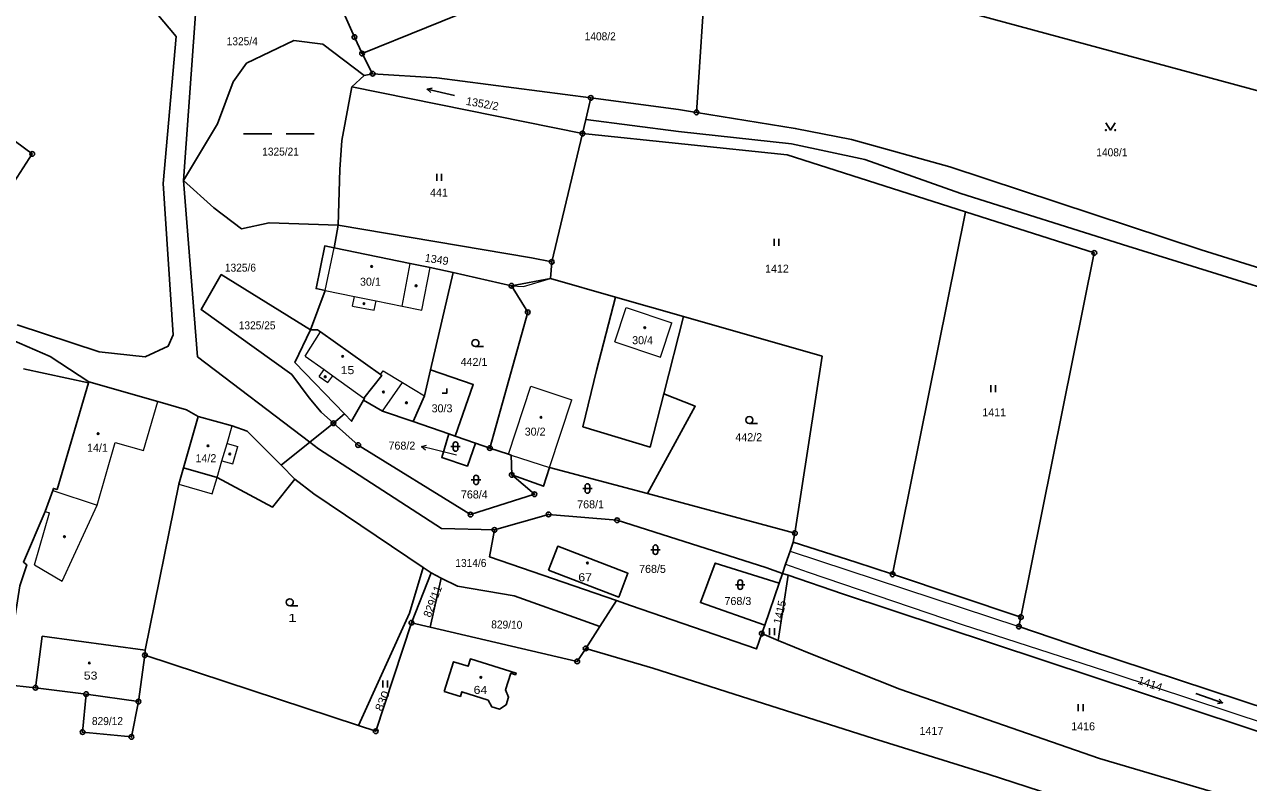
# Model space of a CAD drawing. Extents: x -872229 to -869198, y -1075981 to -1074329.
# Drawn here: x -870924.3 to -870664.3, y -1075366 to -1075205 of the extents above; entities that cross this region are included whole.
import ezdxf
from ezdxf.enums import TextEntityAlignment as Align

# ---------------------------------------------------------------- set-up
doc = ezdxf.new("R2010")
doc.units = 0
doc.header["$LTSCALE"] = 0.68
for name, color, linetype, lineweight in [('1', 7, 'Continuous', 25), ('3', 7, 'Continuous', 25), ('4', 7, 'Continuous', 13), ('5', 7, 'Continuous', 25), ('7', 7, 'Continuous', 13), ('8', 7, 'Continuous', 25)]:
    doc.layers.add(name, color=color, linetype=linetype, lineweight=lineweight)
doc.layers.add('2', color=7, linetype='Continuous')

msp = doc.modelspace()

# ---------------------------------------------------------------- linework, layer by layer
at = {"layer": '1'}
for p, q in [((-870784.32, -1075186.07), (-870610.3, -1075233.15)), ((-870850.35, -1075215.5), (-870852.61, -1075211.21)), ((-870854.77, -1075218.26), (-870852.13, -1075215.85)), ((-870857.69, -1075247.67), (-870858.56, -1075252.46)), ((-870838.03, -1075278.35), (-870833.27, -1075257.72)), ((-870788.49, -1075283.45), (-870784.32, -1075267.06)), ((-870910.7, -1075281.16), (-870924.55, -1075278.18)), ((-870858.68, -1075289.72), (-870856.35, -1075287.73)), ((-870858.68, -1075289.72), (-870863.7, -1075293.77)), ((-870869.76, -1075298.66), (-870863.7, -1075293.77)), ((-870866.86, -1075301.57), (-870869.76, -1075298.66)), ((-870791.98, -1075304.67), (-870760.65, -1075313.06)), ((-870921.99, -1075345.91), (-870928.54, -1075345.19))]:
    msp.add_line(p, q, dxfattribs=at)
for points in [[(-870852.61, -1075211.21), (-870811.58, -1075194.57), (-870784.32, -1075186.07)], [(-870811.58, -1075194.57), (-870779.53, -1075192.5), (-870781.56, -1075223.68)], [(-870925.85, -1075268.83), (-870908.47, -1075274.58), (-870898.66, -1075275.61), (-870893.76, -1075273.35), (-870892.7, -1075270.97), (-870894.88, -1075238.8), (-870892.1, -1075207.59), (-870896.18, -1075202.7), (-870909.34, -1075202.24), (-870920.27, -1075200.54), (-870931.8, -1075197.32)], [(-870882.08, -1075195.84), (-870887.87, -1075200.84), (-870890.54, -1075238.17)], [(-870852.61, -1075211.21), (-870854.23, -1075207.71), (-870856.49, -1075202.6)], [(-870890.54, -1075238.17), (-870883.32, -1075226.14), (-870879.96, -1075217.21), (-870877.12, -1075213.23), (-870867.09, -1075208.41), (-870860.94, -1075209.18), (-870852.13, -1075215.85), (-870850.35, -1075215.5)], [(-870804.02, -1075220.62), (-870836.74, -1075216.34), (-870850.35, -1075215.5)], [(-870857.69, -1075247.67), (-870816.62, -1075254.62), (-870812.3, -1075255.46), (-870805.78, -1075228.2), (-870854.77, -1075218.26)], [(-870854.77, -1075218.26), (-870856.87, -1075229.66), (-870857.34, -1075235.8), (-870857.69, -1075247.67)], [(-870805.78, -1075228.2), (-870805.08, -1075225.21), (-870804.02, -1075220.62)], [(-870781.56, -1075223.68), (-870785.37, -1075223.06), (-870804.02, -1075220.62)], [(-870484.94, -1075312.75), (-870507.19, -1075305.67), (-870536.45, -1075296.46), (-870573.82, -1075284.57), (-870611.19, -1075272.67), (-870674.35, -1075252.89), (-870727.76, -1075235.26), (-870748.62, -1075229.44), (-870760.57, -1075227.08), (-870781.56, -1075223.68)], [(-870805.08, -1075225.21), (-870785.38, -1075227.74), (-870761.4, -1075230.4), (-870745.77, -1075233.67), (-870725.43, -1075240.95), (-870689.94, -1075252.08), (-870636.2, -1075268.85), (-870577.25, -1075287.24), (-870525.79, -1075303.65), (-870498.58, -1075312.54)], [(-870805.78, -1075228.2), (-870762.33, -1075232.72), (-870724.39, -1075244.81)], [(-871072.01, -1075232.97), (-871066.83, -1075229.86), (-871050.73, -1075230.05), (-871024.91, -1075235.65), (-871004.91, -1075242.17), (-870984.75, -1075250.58), (-870962.8, -1075257.63), (-870944.86, -1075263.23), (-870926.98, -1075271.99), (-870918.87, -1075275.55), (-870910.63, -1075280.9)], [(-870863.7, -1075293.77), (-870887.53, -1075275.59), (-870890.54, -1075238.17)], [(-870890.54, -1075238.17), (-870884.1, -1075243.98), (-870878.24, -1075248.43), (-870872.37, -1075247.14), (-870857.69, -1075247.67)], [(-870724.39, -1075244.81), (-870739.92, -1075321.81), (-870712.65, -1075330.89)], [(-870724.39, -1075244.81), (-870697.05, -1075253.53), (-870712.65, -1075330.89)], [(-870858.56, -1075252.46), (-870860.52, -1075252.06), (-870862.38, -1075261.13), (-870860.42, -1075261.53), (-870863.57, -1075269.88)], [(-870833.27, -1075257.72), (-870838.15, -1075256.62), (-870842.37, -1075255.78), (-870858.56, -1075252.46)], [(-870833.27, -1075257.72), (-870820.86, -1075260.51), (-870812.59, -1075258.97), (-870812.3, -1075255.46)], [(-870858.68, -1075289.72), (-870861.31, -1075287.4), (-870863.81, -1075284.33), (-870867.54, -1075279.36), (-870886.81, -1075265.58), (-870882.51, -1075258.13), (-870863.57, -1075269.88)], [(-870812.59, -1075258.97), (-870798.73, -1075262.94), (-870784.32, -1075267.06)], [(-870820.86, -1075260.51), (-870817.4, -1075266.16), (-870825.46, -1075294.99)], [(-870788.49, -1075283.45), (-870791.37, -1075294.77), (-870805.69, -1075290.46), (-870802.78, -1075278.5), (-870798.73, -1075262.94)], [(-870784.32, -1075267.06), (-870754.88, -1075275.48), (-870760.65, -1075313.06), (-870761.04, -1075314.99)], [(-870863.57, -1075269.88), (-870866.86, -1075276.84), (-870856.35, -1075287.73)], [(-870863.57, -1075269.88), (-870862.1, -1075269.86), (-870861.44, -1075270.33), (-870848.69, -1075279.37), (-870848.43, -1075279.55), (-870852.2, -1075284.38), (-870852.07, -1075284.47), (-870852.32, -1075284.82)], [(-870841.73, -1075289.35), (-870839.31, -1075283.9), (-870838.03, -1075278.35)], [(-870832.79, -1075292.45), (-870828.99, -1075281.49), (-870838.03, -1075278.35)], [(-870887.42, -1075288.26), (-870889.87, -1075286.84), (-870896.02, -1075285.08), (-870910.63, -1075280.9), (-870910.7, -1075281.16)], [(-870910.7, -1075281.16), (-870917.39, -1075303.79), (-870918.16, -1075303.57), (-870918.31, -1075303.99), (-870919.9, -1075308.44)], [(-870791.98, -1075304.67), (-870781.81, -1075286.11), (-870788.49, -1075283.45)], [(-870856.35, -1075287.73), (-870854.84, -1075289.29), (-870852.32, -1075284.82)], [(-870852.32, -1075284.82), (-870848.28, -1075287.16), (-870841.73, -1075289.35)], [(-870869.76, -1075298.66), (-870877.02, -1075291.38), (-870880.21, -1075290.3), (-870887.42, -1075288.26), (-870890.53, -1075299.22)], [(-870820.81, -1075300.7), (-870815.99, -1075304.8), (-870829.56, -1075309.11), (-870853.43, -1075294.36), (-870858.68, -1075289.72)], [(-870841.73, -1075289.35), (-870834.19, -1075291.97), (-870832.79, -1075292.45)], [(-870863.7, -1075293.77), (-870861.84, -1075295.19), (-870835.74, -1075312.07), (-870824.47, -1075312.39)], [(-870834.19, -1075291.97), (-870835.68, -1075297.01), (-870830.23, -1075298.81), (-870828.5, -1075293.94)], [(-870832.79, -1075292.45), (-870828.5, -1075293.94), (-870825.46, -1075294.99)], [(-870825.46, -1075294.99), (-870821.46, -1075296.31), (-870820.92, -1075296.51), (-870820.81, -1075300.7)], [(-870898.66, -1075337.89), (-870891.52, -1075302.69), (-870890.53, -1075299.22)], [(-870890.53, -1075299.22), (-870883.4, -1075301.25), (-870871.64, -1075307.56), (-870866.86, -1075301.57)], [(-870820.81, -1075300.7), (-870814.03, -1075303.11), (-870812.79, -1075299.09), (-870791.98, -1075304.67)], [(-870839.61, -1075320.36), (-870862.82, -1075304.74), (-870866.86, -1075301.57)], [(-870919.9, -1075308.44), (-870924.53, -1075319.22), (-870923.81, -1075319.83), (-870925.29, -1075324.27), (-870928.54, -1075345.19)], [(-870824.47, -1075312.39), (-870812.98, -1075309.08), (-870798.44, -1075310.32), (-870766.82, -1075320.38), (-870763.32, -1075321.65)], [(-870798.57, -1075327.39), (-870825.5, -1075318.12), (-870824.47, -1075312.39)], [(-870712.65, -1075330.89), (-870713.06, -1075332.91), (-870698.73, -1075337.79), (-870659.43, -1075350.77), (-870647.08, -1075354.82), (-870636.39, -1075356.51), (-870628.42, -1075355.25), (-870617.68, -1075352.56), (-870583.59, -1075341.47), (-870525.05, -1075322.56), (-870498.58, -1075312.54)], [(-870761.04, -1075314.99), (-870761.68, -1075316.88), (-870762.63, -1075319.63), (-870763.32, -1075321.65), (-870762.07, -1075321.97)], [(-870761.04, -1075314.99), (-870747.73, -1075319.21), (-870739.92, -1075321.81)], [(-870764.02, -1075323.7), (-870777.56, -1075319.43), (-870780.71, -1075327.83), (-870767.06, -1075332.59)], [(-870853.39, -1075353.92), (-870842.55, -1075330.06), (-870839.61, -1075320.36)], [(-870842.12, -1075332.11), (-870837.92, -1075321.5), (-870839.61, -1075320.36)], [(-870838.12, -1075333.04), (-870835.78, -1075322.6), (-870837.92, -1075321.5)], [(-870835.78, -1075322.6), (-870832.36, -1075324.35), (-870820.31, -1075326.41), (-870805.66, -1075331.61), (-870802.09, -1075332.87)], [(-870763.32, -1075321.65), (-870764.02, -1075323.7), (-870767.06, -1075332.59), (-870767.68, -1075334.4), (-870764.18, -1075335.84), (-870762.07, -1075321.97)], [(-870762.07, -1075321.97), (-870750.55, -1075325.97), (-870644.01, -1075361.21), (-870635.72, -1075362.14)], [(-870798.57, -1075327.39), (-870802.09, -1075332.87), (-870805.1, -1075337.55)], [(-870798.57, -1075327.39), (-870795.56, -1075328.43), (-870768.8, -1075337.66), (-870767.68, -1075334.4)], [(-870842.12, -1075332.11), (-870849.71, -1075355.13), (-870853.39, -1075353.92), (-870898.74, -1075339.01)], [(-870805.1, -1075337.55), (-870806.88, -1075340.32), (-870838.12, -1075333.04), (-870842.12, -1075332.11)], [(-870898.66, -1075337.89), (-870920.55, -1075334.96), (-870921.99, -1075345.91)], [(-870921.99, -1075345.91), (-870911.24, -1075347.26), (-870900.1, -1075348.84), (-870898.74, -1075339.01), (-870898.66, -1075337.89)], [(-870805.1, -1075337.55), (-870790.85, -1075341.74), (-870773.54, -1075347.26), (-870743.94, -1075356.68), (-870719.6, -1075364.23), (-870689.31, -1075374.07), (-870671.81, -1075380.32), (-870663.52, -1075383.76), (-870658.58, -1075387.02), (-870652.84, -1075392.9), (-870644.86, -1075404.62), (-870633.82, -1075423.29), (-870622.61, -1075439.76), (-870615.24, -1075449.79), (-870605.9, -1075460.53), (-870599.41, -1075465.72), (-870590.82, -1075469.8), (-870575.95, -1075474.7)], [(-870764.18, -1075335.84), (-870757.26, -1075338.7), (-870738.34, -1075346.2), (-870695.93, -1075360.93), (-870670.53, -1075368.46), (-870660.23, -1075373.2), (-870649.84, -1075380.47), (-870640.68, -1075391.97)], [(-870911.24, -1075347.26), (-870911.97, -1075355.32), (-870901.6, -1075356.36), (-870900.1, -1075348.84)]]:
    msp.add_lwpolyline(points, dxfattribs=at)
for points in [[(-870939.42, -1075220.15), (-870948.22, -1075229.84), (-870930.39, -1075244.42), (-870922.66, -1075232.5)], [(-870812.99, -1075320.94), (-870811.04, -1075315.85), (-870796.14, -1075321.57), (-870798.09, -1075326.66)], [(-870835.15, -1075346.69), (-870833.2, -1075340.38), (-870830.05, -1075341.35), (-870829.57, -1075339.79), (-870819.89, -1075342.79), (-870820.01, -1075343.15), (-870821.02, -1075342.83), (-870822.13, -1075346.38), (-870821.48, -1075347.92), (-870822.01, -1075349.53), (-870823.39, -1075350.47), (-870825.02, -1075349.98), (-870825.84, -1075348.52), (-870831.38, -1075346.75), (-870831.7, -1075347.75)]]:
    msp.add_lwpolyline(points, close=True, dxfattribs=at)
at = {"layer": '3'}
for p, q in [((-870838.798, -1075218.783), (-870837.733, -1075218.514)), ((-870877.759, -1075228.27), (-870871.759, -1075228.27)), ((-870868.759, -1075228.27), (-870862.759, -1075228.27)), ((-870836.751, -1075238.26), (-870836.751, -1075236.76)), ((-870835.75, -1075238.26), (-870835.75, -1075236.76)), ((-870765.051, -1075252.05), (-870765.051, -1075250.55)), ((-870764.05, -1075252.05), (-870764.05, -1075250.55)), ((-870828.523, -1075273.44), (-870826.773, -1075273.44)), ((-870719.011, -1075283.15), (-870719.011, -1075281.65)), ((-870718.01, -1075283.15), (-870718.01, -1075281.65)), ((-870770.343, -1075289.79), (-870768.593, -1075289.79)), ((-870833.741, -1075294.671), (-870831.739, -1075294.671)), ((-870833.241, -1075294.171), (-870833.241, -1075295.172)), ((-870832.239, -1075295.172), (-870832.239, -1075294.171)), ((-870829.391, -1075301.751), (-870827.389, -1075301.751)), ((-870828.891, -1075301.251), (-870828.891, -1075302.252)), ((-870827.889, -1075302.252), (-870827.889, -1075301.251)), ((-870805.721, -1075303.581), (-870803.719, -1075303.581)), ((-870805.221, -1075303.081), (-870805.221, -1075304.082)), ((-870804.219, -1075304.082), (-870804.219, -1075303.081)), ((-870791.281, -1075316.581), (-870789.279, -1075316.581)), ((-870790.781, -1075316.081), (-870790.781, -1075317.082)), ((-870789.779, -1075317.082), (-870789.779, -1075316.081)), ((-870773.271, -1075324.011), (-870771.269, -1075324.011)), ((-870772.771, -1075323.511), (-870772.771, -1075324.512)), ((-870771.769, -1075324.512), (-870771.769, -1075323.511)), ((-870867.963, -1075328.5), (-870866.213, -1075328.5)), ((-870766.021, -1075334.75), (-870766.021, -1075333.25)), ((-870765.02, -1075334.75), (-870765.02, -1075333.25)), ((-870848.171, -1075345.86), (-870848.171, -1075344.36)), ((-870847.17, -1075345.86), (-870847.17, -1075344.36)), ((-870700.451, -1075350.89), (-870700.451, -1075349.39)), ((-870699.45, -1075350.89), (-870699.45, -1075349.39)), ((-870669.79, -1075349.09), (-870670.877, -1075349.246))]:
    msp.add_line(p, q, dxfattribs=at)
for points in [[(-870832.952, -1075220.133), (-870838.798, -1075218.783), (-870837.959, -1075219.491)], [(-870694.6, -1075225.939), (-870693.6, -1075227.44), (-870692.6, -1075225.939)], [(-870835.591, -1075283.33), (-870834.59, -1075283.33), (-870834.59, -1075282.33)], [(-870675.463, -1075347.137), (-870669.79, -1075349.09), (-870670.551, -1075348.298)]]:
    msp.add_lwpolyline(points, dxfattribs=at)
for centre, radius in [((-870694.6, -1075227.4395), 0.1), ((-870692.6, -1075227.4395), 0.1), ((-870828.5229, -1075272.6898), 0.75), ((-870770.3429, -1075289.0398), 0.75), ((-870867.9629, -1075327.7498), 0.75)]:
    msp.add_circle(centre, radius, dxfattribs=at)
for centre, start, end in [((-870832.74, -1075294.1709), 0, 180), ((-870832.74, -1075295.1709), 180, 359.98789), ((-870828.39, -1075301.2509), 0, 180), ((-870828.39, -1075302.2509), 180, 359.98789), ((-870804.72, -1075303.0809), 0, 180), ((-870804.72, -1075304.0809), 180, 359.98789), ((-870790.28, -1075316.0809), 0, 180), ((-870790.28, -1075317.0809), 180, 359.98789), ((-870772.27, -1075323.5109), 0, 180), ((-870772.27, -1075324.5109), 180, 359.98789)]:
    msp.add_arc(centre, 0.5, start, end, dxfattribs=at)
at = {"layer": '4'}
for p, q in [((-870860.42, -1075261.53), (-870858.56, -1075252.46)), ((-870844.1, -1075264.84), (-870842.37, -1075255.78)), ((-870839.87, -1075265.69), (-870838.15, -1075256.62)), ((-870860.42, -1075261.53), (-870854.21, -1075262.79)), ((-870854.65, -1075264.85), (-870850.05, -1075265.73)), ((-870844.1, -1075264.84), (-870839.87, -1075265.69)), ((-870798.93, -1075272.46), (-870796.52, -1075265.16)), ((-870796.52, -1075265.16), (-870786.8, -1075268.38)), ((-870864.7, -1075275.44), (-870861.44, -1075270.33)), ((-870789.18, -1075275.68), (-870786.8, -1075268.38)), ((-870798.93, -1075272.46), (-870789.18, -1075275.68)), ((-870864.7, -1075275.44), (-870860.66, -1075278.33)), ((-870861.69, -1075279.77), (-870859.85, -1075281.09)), ((-870848.69, -1075279.37), (-870848.13, -1075278.57)), ((-870848.13, -1075278.57), (-870843.98, -1075281.08)), ((-870848.28, -1075287.16), (-870843.98, -1075281.08)), ((-870843.98, -1075281.08), (-870839.31, -1075283.9)), ((-870821.46, -1075296.31), (-870816.74, -1075281.81)), ((-870816.74, -1075281.81), (-870808.05, -1075284.73)), ((-870899.02, -1075295.53), (-870896.02, -1075285.08)), ((-870812.79, -1075299.09), (-870808.05, -1075284.73)), ((-870881.29, -1075294.02), (-870880.21, -1075290.3)), ((-870880.04, -1075298.35), (-870878.97, -1075294.69)), ((-870820.92, -1075296.51), (-870812.79, -1075299.09)), ((-870918.31, -1075303.99), (-870908.88, -1075307.14)), ((-870922.2, -1075319.79), (-870918.98, -1075308.77)), ((-870919.9, -1075308.44), (-870918.98, -1075308.77)), ((-870916.32, -1075323.29), (-870908.88, -1075307.14)), ((-870761.68, -1075316.88), (-870713.06, -1075332.91)), ((-870922.2, -1075319.79), (-870916.32, -1075323.29)), ((-870725.1, -1075332.47), (-870692.51, -1075343.01)), ((-870692.51, -1075343.01), (-870660.32, -1075353.61))]:
    msp.add_line(p, q, dxfattribs=at)
for points in [[(-870820.86, -1075260.51), (-870818.3, -1075260.71), (-870812.59, -1075258.97)], [(-870854.65, -1075264.85), (-870854.21, -1075262.79), (-870849.64, -1075263.72)], [(-870850.05, -1075265.73), (-870849.64, -1075263.72), (-870844.1, -1075264.84)], [(-870861.69, -1075279.77), (-870860.66, -1075278.33), (-870858.82, -1075279.65)], [(-870859.85, -1075281.09), (-870858.82, -1075279.65), (-870852.2, -1075284.38)], [(-870908.88, -1075307.14), (-870905.02, -1075293.81), (-870899.02, -1075295.53)], [(-870882.36, -1075297.68), (-870881.29, -1075294.02), (-870878.97, -1075294.69)], [(-870891.52, -1075302.69), (-870884.41, -1075304.73), (-870883.4, -1075301.25), (-870882.36, -1075297.68), (-870880.04, -1075298.35)], [(-870762.63, -1075319.63), (-870757.87, -1075321.38), (-870725.1, -1075332.47)]]:
    msp.add_lwpolyline(points, dxfattribs=at)
at = {"layer": '5'}
for centre in [(-870850.5468, -1075256.4092), (-870841.1168, -1075260.5292), (-870852.1768, -1075264.3292), (-870792.5368, -1075269.4292), (-870856.7368, -1075275.5092), (-870860.4268, -1075279.8492), (-870848.0568, -1075283.0992), (-870843.1768, -1075285.3792), (-870814.6068, -1075288.4492), (-870908.6768, -1075291.9292), (-870885.3168, -1075294.5192), (-870880.6968, -1075296.2492), (-870915.8168, -1075313.8192), (-870804.7168, -1075319.4192), (-870910.5268, -1075340.6392), (-870827.3568, -1075343.6992)]:
    msp.add_circle(centre, 0.175, dxfattribs=at)
at = {"layer": '7'}
msp.add_line((-870839.992, -1075294.644), (-870839.141, -1075295.372), dxfattribs=at)
msp.add_lwpolyline([(-870832.55, -1075296.49), (-870837.08, -1075295.37), (-870839.992, -1075294.644), (-870838.899, -1075294.4)], dxfattribs=at)
at = {"layer": '8'}
for centre, radius in [((-870854.23, -1075207.7099), 0.5), ((-870854.23, -1075207.7099), 0.0303), ((-870852.61, -1075211.2099), 0.5), ((-870852.61, -1075211.2099), 0.0303), ((-870850.35, -1075215.4999), 0.5), ((-870850.35, -1075215.4999), 0.0303), ((-870804.02, -1075220.6199), 0.5), ((-870804.02, -1075220.6199), 0.0303), ((-870781.56, -1075223.6799), 0.5), ((-870781.56, -1075223.6799), 0.0303), ((-870805.78, -1075228.1999), 0.5), ((-870805.78, -1075228.1999), 0.0303), ((-870922.66, -1075232.4999), 0.5), ((-870922.66, -1075232.4999), 0.0303), ((-870812.3, -1075255.4599), 0.5), ((-870697.05, -1075253.5299), 0.5), ((-870697.05, -1075253.5299), 0.0303), ((-870812.3, -1075255.4599), 0.0303), ((-870820.86, -1075260.5099), 0.5), ((-870820.86, -1075260.5099), 0.0303), ((-870817.4, -1075266.1599), 0.5), ((-870817.4, -1075266.1599), 0.0303), ((-870858.68, -1075289.7199), 0.5), ((-870858.68, -1075289.7199), 0.0303), ((-870853.43, -1075294.3599), 0.5), ((-870853.43, -1075294.3599), 0.0303), ((-870825.46, -1075294.9899), 0.5), ((-870825.46, -1075294.9899), 0.0303), ((-870820.81, -1075300.6999), 0.5), ((-870820.81, -1075300.6999), 0.0303), ((-870815.99, -1075304.7999), 0.5), ((-870815.99, -1075304.7999), 0.0303), ((-870829.56, -1075309.1099), 0.5), ((-870829.56, -1075309.1099), 0.0303), ((-870812.98, -1075309.0799), 0.5), ((-870812.98, -1075309.0799), 0.0303), ((-870824.47, -1075312.3899), 0.5), ((-870798.44, -1075310.3199), 0.5), ((-870798.44, -1075310.3199), 0.0303), ((-870824.47, -1075312.3899), 0.0303), ((-870760.65, -1075313.0599), 0.5), ((-870760.65, -1075313.0599), 0.0303), ((-870739.92, -1075321.8099), 0.5), ((-870739.92, -1075321.8099), 0.0303), ((-870712.65, -1075330.8899), 0.5), ((-870842.12, -1075332.1099), 0.5), ((-870842.12, -1075332.1099), 0.0303), ((-870713.06, -1075332.9099), 0.5), ((-870713.06, -1075332.9099), 0.0303), ((-870712.65, -1075330.8899), 0.0303), ((-870767.68, -1075334.3999), 0.5), ((-870767.68, -1075334.3999), 0.0303), ((-870805.1, -1075337.5499), 0.5), ((-870805.1, -1075337.5499), 0.0303), ((-870898.74, -1075339.0099), 0.5), ((-870898.74, -1075339.0099), 0.0303), ((-870806.88, -1075340.3199), 0.5), ((-870806.88, -1075340.3199), 0.0303), ((-870921.99, -1075345.9099), 0.5), ((-870921.99, -1075345.9099), 0.0303), ((-870911.24, -1075347.2599), 0.5), ((-870911.24, -1075347.2599), 0.0303), ((-870900.1, -1075348.8399), 0.5), ((-870900.1, -1075348.8399), 0.0303), ((-870911.97, -1075355.3199), 0.5), ((-870911.97, -1075355.3199), 0.0303), ((-870901.6, -1075356.3599), 0.5), ((-870901.6, -1075356.3599), 0.0303), ((-870849.71, -1075355.1299), 0.5), ((-870849.71, -1075355.1299), 0.0303)]:
    msp.add_circle(centre, radius, dxfattribs=at)

# ---------------------------------------------------------------- texts
at = {"layer": '2'}
for s, width, p in [('1325/4', 0.95, (-870881.36, -1075209.43)), ('1325/21', 0.95, (-870873.82, -1075232.87)), ('1325/6', 0.95, (-870881.74, -1075257.52)), ('1325/25', 0.95, (-870878.8, -1075269.78)), ('15', 1.15, (-870857.16, -1075279.29)), ('1314/6', 0.95, (-870832.79, -1075320.25)), ('1', 1.45, (-870868.33, -1075331.91)), ('53', 1.15, (-870911.72, -1075344.17)), ('829/12', 0.95, (-870909.99, -1075353.83))]:
    msp.add_text(s, height=1.7, dxfattribs=dict(at, width=width)).set_placement(p)
for s, width, p in [('1408/2', 0.95, (-870802.009, -1075208.39)), ('1408/1', 0.95, (-870693.319, -1075233.03)), ('67', 1.15, (-870805.21, -1075323.28)), ('64', 1.15, (-870827.45, -1075347.21))]:
    msp.add_text(s, height=1.7, dxfattribs=dict(at, width=width)).set_placement(p, align=Align.CENTER)
for s, rotation, p in [('1352/2', 350, (-870830.617, -1075222.077)), ('1349', 351, (-870839.372, -1075255.369)), ('829/11', 69, (-870838.076, -1075331.104)), ('1415', 77, (-870763.621, -1075332.521))]:
    msp.add_text(s, height=1.7, rotation=rotation, dxfattribs=at).set_placement(p)
for s, p in [('441', (-870838.16, -1075241.58)), ('1412', (-870767, -1075257.74)), ('30/1', (-870853.04, -1075260.51)), ('30/4', (-870795.23, -1075272.93)), ('442/1', (-870831.67, -1075277.55)), ('30/3', (-870837.83, -1075287.4)), ('1411', (-870720.85, -1075288.26)), ('30/2', (-870818.05, -1075292.35)), ('14/1', (-870911.03, -1075295.79)), ('442/2', (-870773.3, -1075293.53)), ('14/2', (-870887.98, -1075297.99)), ('768/4', (-870831.6, -1075305.7)), ('768/1', (-870806.9, -1075307.79)), ('768/5', (-870793.75, -1075321.51)), ('768/3', (-870775.61, -1075328.33)), ('1416', (-870701.96, -1075354.95)), ('1417', (-870734.18, -1075355.93))]:
    msp.add_text(s, height=1.7, dxfattribs=at).set_placement(p)
msp.add_text('768/2', height=1.7, dxfattribs=at).set_placement((-870844.14, -1075295.32), align=Align.CENTER)
for s, rotation, width, p in [('829/10', 359, 0.95, (-870825.174, -1075333.289)), ('1414', 341, 1.05, (-870687.966, -1075344.993)), ('830', 67, 1.15, (-870848.377, -1075351.052))]:
    msp.add_text(s, height=1.7, rotation=rotation, dxfattribs=dict(at, width=width)).set_placement(p)

doc.saveas('drawing.dxf')
